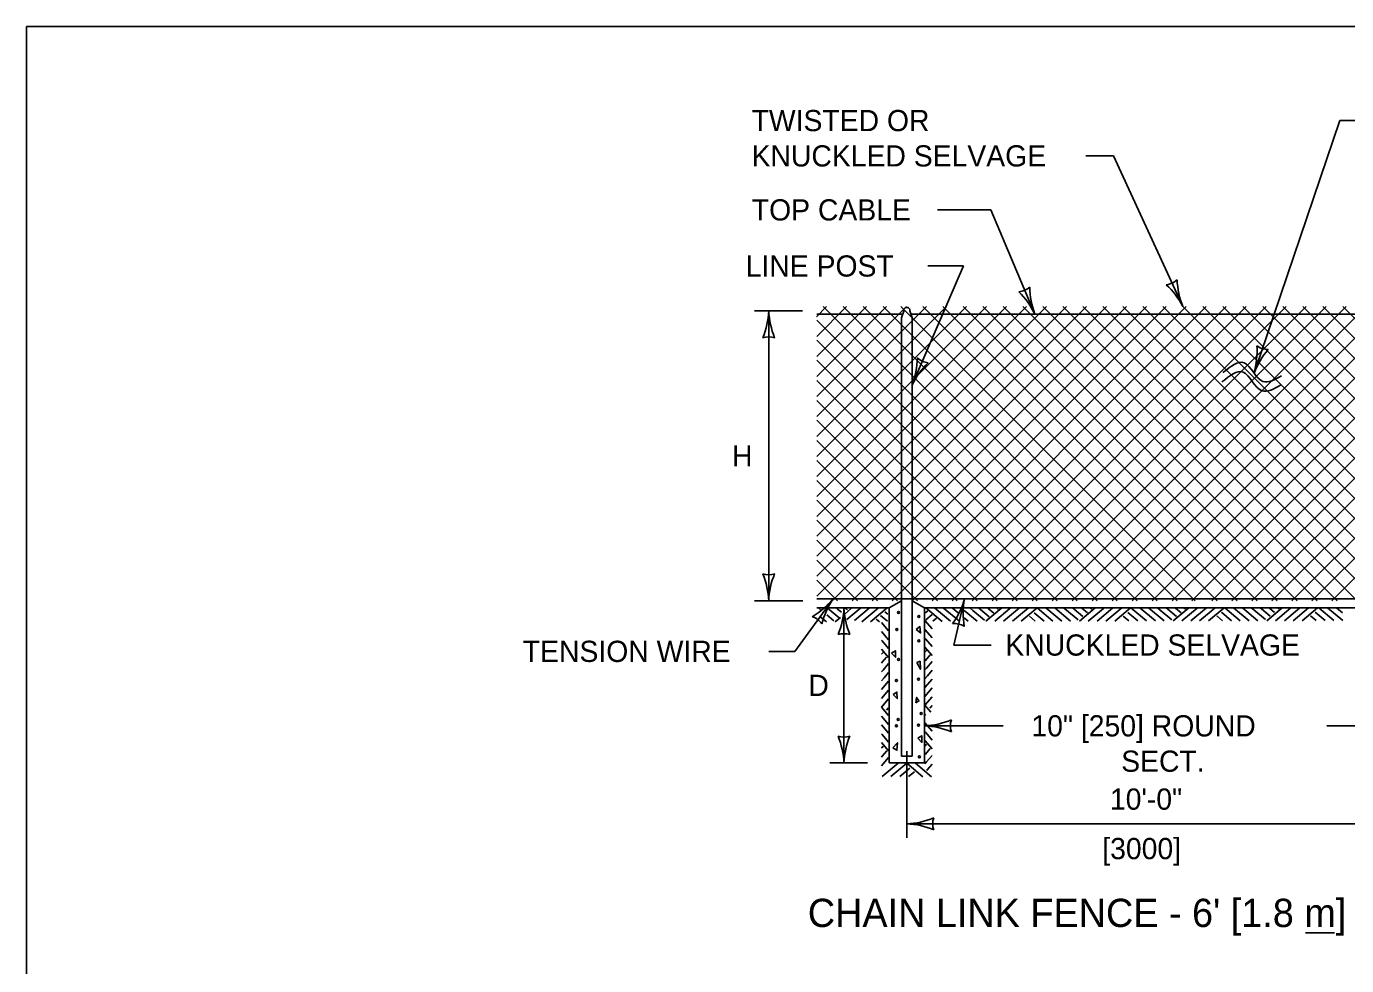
# Model space of a CAD drawing. Extents: x 49973.1 to 50021, y 49987.6 to 50015.4.
# Drawn here: x 49999.384 to 50003.121, y 49996.342 to 49998.999 of the extents above; entities that cross this region are included whole.
import ezdxf

# ---------------------------------------------------------------- set-up
doc = ezdxf.new("R2010")
doc.units = 0
for name, color, linetype in [('Level 1', 7, 'Continuous'), ('Level 2', 7, 'Continuous'), ('Level 3', 7, 'Continuous'), ('Level 6', 7, 'Continuous')]:
    doc.layers.add(name, color=color, linetype=linetype)

msp = doc.modelspace()

# ---------------------------------------------------------------- linework, layer by layer
at = {"layer": 'Level 1'}
for p, q in [((50001.62, 49998.1775), (50001.6487, 49998.2062)), ((50001.6208, 49998.1217), (50001.7053, 49998.2062)), ((50001.6208, 49998.0651), (50001.7619, 49998.2062)), ((50001.6208, 49998.0085), (50001.8185, 49998.2062)), ((50001.6209, 49997.9522), (50001.8749, 49998.2062)), ((50001.6209, 49997.8956), (50001.9315, 49998.2062)), ((50001.6209, 49997.6692), (50002.1579, 49998.2062)), ((50001.6209, 49997.6128), (50002.2143, 49998.2062)), ((50001.6209, 49997.7824), (50002.0447, 49998.2062)), ((50001.6209, 49997.7258), (50002.1013, 49998.2062)), ((50001.6209, 49997.839), (50001.9881, 49998.2062)), ((50001.621, 49997.5563), (50002.2709, 49998.2062)), ((50001.621, 49997.4431), (50002.3841, 49998.2062)), ((50001.621, 49997.4997), (50002.3275, 49998.2062)), ((50001.621, 49997.3865), (50002.4407, 49998.2062)), ((50001.639, 49998.2062), (50002.4716, 49997.3738)), ((50001.6649, 49997.3738), (50002.4973, 49998.2062)), ((50001.6958, 49998.2062), (50002.5282, 49997.3738)), ((50001.7215, 49997.3738), (50002.5539, 49998.2062)), ((50001.7522, 49998.2062), (50002.5848, 49997.3738)), ((50001.7779, 49997.3738), (50002.6103, 49998.2062)), ((50001.8088, 49998.2062), (50002.6414, 49997.3738)), ((50001.8345, 49997.3738), (50002.6669, 49998.2062)), ((50001.8593, 49998.2062), (50002.6922, 49997.3738)), ((50001.8608, 49998.1741), (50001.8671, 49998.1936)), ((50001.8908, 49998.1741), (50001.8848, 49998.1939)), ((50001.8911, 49997.3738), (50002.7235, 49998.2062)), ((50001.9213, 49998.2062), (50002.7544, 49997.3738)), ((50001.9477, 49997.3738), (50002.7801, 49998.2062)), ((50001.9781, 49998.2062), (50002.811, 49997.3738)), ((50002.0043, 49997.3738), (50002.8367, 49998.2062)), ((50002.0349, 49998.2062), (50002.8676, 49997.3738)), ((50002.0609, 49997.3738), (50002.8933, 49998.2062)), ((50002.0913, 49998.2062), (50002.9242, 49997.3738)), ((50002.1173, 49997.3738), (50002.9497, 49998.2062)), ((50002.1482, 49998.2062), (50002.9808, 49997.3738)), ((50002.1739, 49997.3738), (50003.0063, 49998.2062)), ((50002.2043, 49998.2062), (50003.0372, 49997.3738)), ((50002.2305, 49997.3738), (50003.0629, 49998.2062)), ((50002.2607, 49998.2062), (50003.0938, 49997.3738)), ((50002.2871, 49997.3738), (50003.1195, 49998.2062)), ((50002.3178, 49998.2062), (50003.1504, 49997.3738)), ((50002.3437, 49997.3738), (50003.1761, 49998.2062)), ((50002.3741, 49998.2062), (50003.207, 49997.3738)), ((50002.4003, 49997.3738), (50003.2327, 49998.2062)), ((50002.431, 49998.2062), (50003.2636, 49997.3738)), ((50002.4567, 49997.3738), (50003.2891, 49998.2062)), ((50002.4876, 49998.2062), (50003.3202, 49997.3738)), ((50002.5133, 49997.3738), (50003.3457, 49998.2062)), ((50002.5441, 49998.2062), (50003.3768, 49997.3738)), ((50002.5699, 49997.3738), (50003.4023, 49998.2062)), ((50002.6006, 49998.2062), (50003.4332, 49997.3738)), ((50002.6265, 49997.3738), (50003.4589, 49998.2062)), ((50002.6574, 49998.2062), (50003.4898, 49997.3738)), ((50002.6831, 49997.3738), (50003.5155, 49998.2062)), ((50002.7139, 49998.2062), (50003.5464, 49997.3738)), ((50002.7397, 49997.3738), (50003.5721, 49998.2062)), ((50002.7705, 49998.2062), (50003.603, 49997.3738)), ((50002.7963, 49997.3738), (50003.6287, 49998.2062)), ((50002.8271, 49998.2062), (50003.6596, 49997.3738)), ((50002.8527, 49997.3738), (50003.6851, 49998.2062)), ((50002.8837, 49998.2062), (50003.7162, 49997.3738)), ((50002.9093, 49997.3738), (50003.7417, 49998.2062)), ((50002.9401, 49998.2062), (50003.7726, 49997.3738)), ((50002.9659, 49997.3738), (50003.7983, 49998.2062)), ((50002.9967, 49998.2062), (50003.8292, 49997.3738)), ((50003.0225, 49997.3738), (50003.8549, 49998.2062)), ((50003.0533, 49998.2062), (50003.8858, 49997.3738)), ((50003.0791, 49997.3738), (50003.9115, 49998.2062)), ((50003.1099, 49998.2062), (50003.9424, 49997.3738)), ((50001.6208, 49998.1849), (50001.8643, 49998.1849)), ((50001.6208, 49998.1677), (50002.415, 49997.3738)), ((50001.8608, 49998.1741), (50001.8608, 49996.9341)), ((50001.8875, 49998.1849), (50003.2643, 49998.1849)), ((50001.8908, 49998.1741), (50001.8908, 49996.9341)), ((50001.6208, 49998.1111), (50002.3584, 49997.3738)), ((50001.6208, 49998.0543), (50002.3018, 49997.3738)), ((50001.6208, 49997.9975), (50002.2452, 49997.3738)), ((50001.6209, 49997.941), (50002.1886, 49997.3738)), ((50001.6209, 49997.8847), (50002.132, 49997.3738)), ((50001.6209, 49997.8275), (50002.0754, 49997.3738)), ((50001.6209, 49997.7712), (50002.0188, 49997.3738)), ((50001.6209, 49997.7147), (50001.9622, 49997.3738)), ((50001.6209, 49997.6584), (50001.9056, 49997.3738)), ((50001.6209, 49997.6017), (50001.849, 49997.3738)), ((50001.621, 49997.5451), (50001.7924, 49997.3738)), ((50001.621, 49997.4885), (50001.7358, 49997.3738)), ((50001.621, 49997.4319), (50001.6792, 49997.3738)), ((50001.6211, 49997.3795), (50004.6137, 49997.3795)), ((50001.8258, 49997.3541), (50001.8608, 49997.3741)), ((50001.9258, 49997.354), (50001.8908, 49997.3734)), ((50001.621, 49997.3541), (50001.8258, 49997.3541)), ((50001.6316, 49997.3487), (50001.6266, 49997.3529)), ((50001.6481, 49997.314), (50001.6293, 49997.3297)), ((50001.6317, 49997.3487), (50001.6317, 49997.3487)), ((50001.6691, 49997.3175), (50001.6491, 49997.3342)), ((50001.6504, 49997.354), (50001.6503, 49997.3541)), ((50001.684, 49997.3259), (50001.6506, 49997.3541)), ((50001.6797, 49997.3504), (50001.6758, 49997.3537)), ((50001.6907, 49997.3412), (50001.6797, 49997.3504)), ((50001.7009, 49997.3374), (50001.7193, 49997.3528)), ((50001.7031, 49997.3517), (50001.701, 49997.3534)), ((50001.7081, 49997.3475), (50001.7031, 49997.3517)), ((50001.7057, 49997.3205), (50001.7458, 49997.3541)), ((50001.7275, 49997.3179), (50001.7693, 49997.3528)), ((50001.7382, 49997.3477), (50001.7411, 49997.3501)), ((50001.7411, 49997.3501), (50001.7437, 49997.3523)), ((50001.7481, 49997.314), (50001.7959, 49997.3541)), ((50001.7731, 49997.314), (50001.8201, 49997.3535)), ((50001.8208, 49997.3159), (50001.801, 49997.3326)), ((50001.8219, 49997.336), (50001.8139, 49997.3427)), ((50001.8258, 49997.3541), (50001.8258, 49996.915)), ((50001.9258, 49997.3541), (50003.2258, 49997.3541)), ((50001.9258, 49996.915), (50001.9258, 49997.354)), ((50001.9284, 49997.3402), (50001.935, 49997.3457)), ((50001.9296, 49997.3202), (50001.9475, 49997.3352)), ((50001.9757, 49997.3149), (50001.9297, 49997.3535)), ((50001.9995, 49997.3159), (50001.9539, 49997.3541)), ((50002.0245, 49997.3159), (50001.9791, 49997.354)), ((50002.0208, 49997.34), (50002.004, 49997.354)), ((50002.0745, 49997.3159), (50002.038, 49997.3465)), ((50002.0631, 49997.3464), (50002.0539, 49997.354)), ((50002.0954, 49997.3193), (50002.0631, 49997.3464)), ((50002.0847, 49997.3493), (50002.079, 49997.354)), ((50002.1093, 49997.3287), (50002.0847, 49997.3493)), ((50002.0995, 49997.3159), (50002.1448, 49997.354)), ((50002.1061, 49997.3523), (50002.104, 49997.354)), ((50002.1218, 49997.3392), (50002.1061, 49997.3523)), ((50002.1245, 49997.3159), (50002.1675, 49997.352)), ((50002.1295, 49997.3536), (50002.129, 49997.354)), ((50002.1345, 49997.3494), (50002.1295, 49997.3536)), ((50002.1495, 49997.3159), (50002.1948, 49997.354)), ((50002.1675, 49997.352), (50002.1698, 49997.354)), ((50002.1745, 49997.3159), (50002.2198, 49997.354)), ((50002.1995, 49997.3159), (50002.2448, 49997.354)), ((50002.2396, 49997.3164), (50002.2233, 49997.3301)), ((50002.2646, 49997.3164), (50002.2362, 49997.3402)), ((50002.2896, 49997.3164), (50002.2448, 49997.354)), ((50002.3146, 49997.3164), (50002.2696, 49997.354)), ((50002.3396, 49997.3164), (50002.2946, 49997.354)), ((50002.3282, 49997.3469), (50002.3196, 49997.354)), ((50002.3605, 49997.3198), (50002.3282, 49997.3469)), ((50002.3498, 49997.3498), (50002.3447, 49997.354)), ((50002.3744, 49997.3292), (50002.3498, 49997.3498)), ((50002.3646, 49997.3164), (50002.4093, 49997.354)), ((50002.3712, 49997.3528), (50002.3697, 49997.354)), ((50002.3869, 49997.3397), (50002.3712, 49997.3528)), ((50002.3896, 49997.3164), (50002.4326, 49997.3525)), ((50002.3996, 49997.3499), (50002.3946, 49997.3541)), ((50002.4146, 49997.3164), (50002.4593, 49997.354)), ((50002.4326, 49997.3525), (50002.4343, 49997.354)), ((50002.4396, 49997.3164), (50002.4843, 49997.354)), ((50002.4646, 49997.3164), (50002.5093, 49997.354)), ((50002.5047, 49997.3169), (50002.4884, 49997.3306)), ((50002.5297, 49997.3169), (50002.5013, 49997.3407)), ((50002.5547, 49997.3169), (50002.5104, 49997.354)), ((50002.5797, 49997.3169), (50002.5353, 49997.354)), ((50002.6047, 49997.3169), (50002.5603, 49997.354)), ((50002.5933, 49997.3474), (50002.5853, 49997.354)), ((50002.6256, 49997.3203), (50002.5933, 49997.3474)), ((50002.6149, 49997.3503), (50002.6104, 49997.354)), ((50002.6395, 49997.3297), (50002.6149, 49997.3503)), ((50002.6297, 49997.3169), (50002.6738, 49997.354)), ((50002.6363, 49997.3533), (50002.6354, 49997.354)), ((50002.652, 49997.3402), (50002.6363, 49997.3533)), ((50002.6547, 49997.3169), (50002.6977, 49997.353)), ((50002.6647, 49997.3504), (50002.6604, 49997.354)), ((50002.6797, 49997.3169), (50002.7238, 49997.354)), ((50002.6977, 49997.353), (50002.6988, 49997.354)), ((50002.7047, 49997.3169), (50002.7488, 49997.354)), ((50002.7297, 49997.3169), (50002.7738, 49997.354)), ((50002.7698, 49997.3174), (50002.7535, 49997.3311)), ((50002.7948, 49997.3174), (50002.7664, 49997.3412)), ((50002.8198, 49997.3174), (50002.7761, 49997.354)), ((50002.8448, 49997.3174), (50002.801, 49997.354)), ((50002.8698, 49997.3174), (50002.826, 49997.354)), ((50002.8584, 49997.3479), (50002.851, 49997.354)), ((50002.8907, 49997.3208), (50002.8584, 49997.3479)), ((50002.88, 49997.3508), (50002.8761, 49997.354)), ((50002.9046, 49997.3302), (50002.88, 49997.3508)), ((50002.8948, 49997.3174), (50002.9383, 49997.354)), ((50002.9014, 49997.3538), (50002.9011, 49997.354)), ((50002.9171, 49997.3407), (50002.9014, 49997.3538)), ((50002.9198, 49997.3174), (50002.9628, 49997.3535)), ((50002.9298, 49997.3509), (50002.9261, 49997.354)), ((50002.9448, 49997.3174), (50002.9883, 49997.354)), ((50002.9628, 49997.3535), (50002.9633, 49997.354)), ((50002.9698, 49997.3174), (50003.0133, 49997.354)), ((50002.9948, 49997.3174), (50003.0383, 49997.354)), ((50003.0349, 49997.3179), (50003.0186, 49997.3316)), ((50003.0599, 49997.3179), (50003.0315, 49997.3417)), ((50003.0849, 49997.3179), (50003.0418, 49997.354)), ((50003.1099, 49997.3179), (50003.0667, 49997.354)), ((50003.1091, 49997.3395), (50003.0917, 49997.354)), ((50001.6731, 49997.314), (50001.6877, 49997.3263)), ((50001.7981, 49997.314), (50001.7888, 49997.3218)), ((50001.8242, 49997.2884), (50001.8043, 49997.3121)), ((50001.9471, 49997.2943), (50001.9272, 49997.318)), ((50001.9471, 49997.2693), (50001.9272, 49997.293)), ((50001.9495, 49997.3159), (50001.9597, 49997.3244)), ((50002.0495, 49997.3159), (50002.038, 49997.3255)), ((50001.8242, 49997.2634), (50001.8043, 49997.2871)), ((50001.8058, 49997.2604), (50001.8043, 49997.2621)), ((50001.8242, 49997.2384), (50001.8058, 49997.2604)), ((50001.9287, 49997.2663), (50001.9272, 49997.268)), ((50001.9471, 49997.2443), (50001.9287, 49997.2663)), ((50001.8084, 49997.2274), (50001.8042, 49997.2224)), ((50001.8242, 49997.2134), (50001.8043, 49997.2371)), ((50001.9313, 49997.2333), (50001.9271, 49997.2283)), ((50001.9471, 49997.2193), (50001.9272, 49997.243)), ((50001.9415, 49997.2206), (50001.9284, 49997.2049)), ((50001.8055, 49997.199), (50001.8043, 49997.1975)), ((50001.8186, 49997.2147), (50001.8055, 49997.199)), ((50001.8242, 49997.1963), (50001.8085, 49997.1776)), ((50001.9284, 49997.2049), (50001.9272, 49997.2034)), ((50001.9314, 49997.1835), (50001.9272, 49997.1784)), ((50001.9471, 49997.2022), (50001.9314, 49997.1835)), ((50001.8085, 49997.1776), (50001.8043, 49997.1725)), ((50001.8114, 49997.156), (50001.8043, 49997.1474)), ((50001.8242, 49997.1462), (50001.8043, 49997.1224)), ((50001.8242, 49997.1712), (50001.8114, 49997.156)), ((50001.9343, 49997.1619), (50001.9272, 49997.1533)), ((50001.9471, 49997.1521), (50001.9272, 49997.1283)), ((50001.9471, 49997.1771), (50001.9343, 49997.1619)), ((50001.8242, 49997.1212), (50001.8043, 49997.0974)), ((50001.9471, 49997.1271), (50001.9272, 49997.1033)), ((50001.8242, 49997.0963), (50001.8043, 49997.0726)), ((50001.8242, 49997.0489), (50001.8043, 49997.0726)), ((50001.8242, 49997.0712), (50001.8181, 49997.064)), ((50001.9471, 49997.1022), (50001.9272, 49997.0785)), ((50001.944, 49997.0585), (50001.9272, 49997.0785)), ((50001.9471, 49997.0771), (50001.941, 49997.0699)), ((50001.8242, 49997.0239), (50001.8043, 49997.0476)), ((50001.9296, 49997.0506), (50001.9272, 49997.0535)), ((50001.8242, 49996.9989), (50001.8043, 49997.0226)), ((50001.8063, 49996.9953), (50001.8043, 49996.9976)), ((50001.8242, 49996.9739), (50001.8063, 49996.9953)), ((50001.9471, 49997.0048), (50001.9272, 49997.0285)), ((50001.9292, 49997.0012), (50001.9272, 49997.0035)), ((50001.9471, 49996.9798), (50001.9292, 49997.0012)), ((50001.8242, 49996.9489), (50001.8043, 49996.9726)), ((50001.8047, 49996.9573), (50001.8043, 49996.9568)), ((50001.8089, 49996.9623), (50001.8047, 49996.9573)), ((50001.9471, 49996.9548), (50001.9272, 49996.9785)), ((50001.9276, 49996.9632), (50001.9272, 49996.9627)), ((50001.9318, 49996.9682), (50001.9276, 49996.9632)), ((50001.942, 49996.9555), (50001.9289, 49996.9398)), ((50001.806, 49996.9339), (50001.8043, 49996.9318)), ((50001.8191, 49996.9496), (50001.806, 49996.9339)), ((50001.8242, 49996.9306), (50001.809, 49996.9125)), ((50001.8608, 49996.9341), (50001.8908, 49996.9341)), ((50001.9289, 49996.9398), (50001.9272, 49996.9377)), ((50001.9319, 49996.9184), (50001.9272, 49996.9127)), ((50001.9471, 49996.9365), (50001.9319, 49996.9184)), ((50001.809, 49996.9125), (50001.8043, 49996.9068)), ((50001.8059, 49996.8766), (50001.8509, 49996.9142)), ((50001.8258, 49996.915), (50001.9258, 49996.915)), ((50001.8309, 49996.8766), (50001.8757, 49996.9142)), ((50001.8559, 49996.8766), (50001.8843, 49996.9004)), ((50001.921, 49996.8761), (50001.8757, 49996.9142)), ((50001.8809, 49996.8766), (50001.8972, 49996.8903)), ((50001.946, 49996.8761), (50001.9007, 49996.9142)), ((50001.9348, 49996.8968), (50001.9324, 49996.8939)), ((50001.9471, 49996.9114), (50001.9348, 49996.8968))]:
    msp.add_line(p, q, dxfattribs=at)
for points in [[(49999.3835, 49998.9992), (50016.7501, 49998.9992), (50016.7501, 49987.7988), (49999.3835, 49987.7988)], [(50001.9018, 49997.2928), (50001.9128, 49997.301), (50001.9149, 49997.2831)], [(50001.8323, 49997.2258), (50001.8433, 49997.2327), (50001.844, 49997.2142)], [(50001.9039, 49997.1995), (50001.9135, 49997.203), (50001.9142, 49997.1803)], [(50001.8368, 49997.1087), (50001.8478, 49997.1156), (50001.8485, 49997.0971)], [(50001.9013, 49997.0848), (50001.9034, 49997.1005), (50001.9102, 49997.0903)], [(50001.8366, 49996.9577), (50001.849, 49996.9721), (50001.8476, 49996.9509)], [(50001.907, 49996.9849), (50001.918, 49996.9918), (50001.9187, 49996.9733)]]:
    msp.add_lwpolyline(points, close=True, dxfattribs=at)
for centre in [(50001.8526, 49997.3408), (50001.91, 49997.3293), (50001.8475, 49997.2923), (50001.91, 49997.2604), (50001.8526, 49997.208), (50001.8462, 49997.148), (50001.9088, 49997.1519), (50001.8513, 49997.0382), (50001.9164, 49997.0548), (50001.8462, 49997.0204), (50001.9088, 49997.0217), (50001.9113, 49996.9323)]:
    msp.add_circle(centre, 0.00279, dxfattribs=at)
msp.add_arc((50001.8759, 49998.1951), 0.00895, 352.3754, 189.572, dxfattribs=at)
at = {"layer": 'Level 2'}
msp.add_line((50003.0863, 49996.4347), (50003.0044, 49996.4347), dxfattribs=at)
at = {"layer": 'Level 3'}
for p, q in [((50002.8588, 49998.018), (50003.1019, 49998.7328)), ((50003.1019, 49998.7328), (50003.2208, 49998.7328)), ((50002.4613, 49998.6328), (50002.3825, 49998.6328)), ((50002.6574, 49998.2062), (50002.4613, 49998.6328)), ((50002.1132, 49998.48), (50001.9625, 49998.48)), ((50002.2382, 49998.1849), (50002.1132, 49998.48)), ((50001.8908, 49997.9845), (50002.0365, 49998.3213)), ((50002.0365, 49998.3213), (50001.9349, 49998.3213)), ((50001.5808, 49998.1941), (50001.4449, 49998.1941)), ((50001.4849, 49997.3741), (50001.4849, 49998.1941)), ((50001.5811, 49997.3741), (50001.4449, 49997.3741)), ((50001.6674, 49997.3795), (50001.5585, 49997.2308)), ((50002.0391, 49997.3795), (50002.0085, 49997.2481)), ((50001.6979, 49996.915), (50001.6979, 49997.3541)), ((50001.5585, 49997.2308), (50001.4849, 49997.2308)), ((50002.0085, 49997.2481), (50002.1146, 49997.2481)), ((50002.1483, 49997.02), (50001.9258, 49997.02)), ((50003.065, 49997.02), (50003.2258, 49997.02)), ((50001.8758, 49996.948), (50001.8758, 49996.7027)), ((50001.7643, 49996.915), (50001.6579, 49996.915)), ((50001.8758, 49996.7427), (50003.2767, 49996.7427))]:
    msp.add_line(p, q, dxfattribs=at)
for centre, radius, start, end in [((50002.6039, 49998.3227), 0.0548, 276.8211, 312.5434), ((50002.4507, 49998.0986), 0.233, 27.5096, 46.7594), ((50002.8631, 49998.2907), 0.2223, 182.1383, 202.3218), ((50002.1882, 49998.303), 0.0548, 275.0872, 310.8096), ((50002.0284, 49998.0836), 0.233, 25.7757, 45.0255), ((50002.4463, 49998.2631), 0.2223, 180.4044, 200.5879), ((50001.2628, 49998.2033), 0.2223, 337.456, 357.6395), ((50001.7176, 49998.2056), 0.233, 182.8273, 202.0772), ((50001.4849, 49998.0659), 0.0548, 72.1388, 107.8612), ((50002.6345, 49998.0814), 0.233, 344.2336, 3.4835), ((50003.0664, 49997.9385), 0.2223, 138.8623, 159.0459), ((50002.8997, 49998.1396), 0.0548, 233.5452, 269.2675), ((50001.6727, 49998.0664), 0.233, 339.4345, 358.6844), ((50002.091, 49997.8879), 0.2223, 134.0632, 154.2467), ((50001.9417, 49998.1022), 0.0548, 228.746, 264.4684), ((50001.4849, 49997.5023), 0.0548, 252.1388, 287.8612), ((50001.2522, 49997.3626), 0.233, 2.8273, 22.0772), ((50001.707, 49997.365), 0.2223, 157.456, 177.6395), ((50001.4954, 49997.5204), 0.2223, 300.5072, 320.6907), ((50001.8603, 49997.2488), 0.233, 145.8785, 165.1283), ((50001.8248, 49997.4388), 0.2223, 324.3468, 344.5303), ((50002.2683, 49997.3379), 0.233, 169.7181, 188.968), ((50001.4758, 49997.3633), 0.2223, 337.456, 357.6395), ((50001.9306, 49997.3656), 0.233, 182.8273, 202.0772), ((50001.5903, 49997.2771), 0.0548, 35.19, 70.9123), ((50002.01, 49997.2547), 0.0548, 59.0296, 94.752), ((50001.6979, 49997.2259), 0.0548, 72.1388, 107.8612), ((50001.9143, 49997.2527), 0.233, 272.8273, 292.0772), ((50002.054, 49997.02), 0.0548, 162.1388, 197.8612), ((50001.9166, 49996.7979), 0.2223, 67.456, 87.6395), ((50001.6979, 49997.0432), 0.0548, 252.1388, 287.8612), ((50001.4652, 49996.9035), 0.233, 2.8273, 22.0772), ((50001.92, 49996.9059), 0.2223, 157.456, 177.6395), ((50001.8643, 49996.9754), 0.233, 272.8273, 292.0772), ((50001.8666, 49996.5206), 0.2223, 67.456, 87.6395), ((50002.004, 49996.7427), 0.0548, 162.1388, 197.8612)]:
    msp.add_arc(centre, radius, start, end, dxfattribs=at)
at = {"layer": 'Level 6'}
for points in [[(50002.7705, 49998.0195), (50002.8307, 49998.0474), (50002.8837, 49997.9946), (50002.9366, 49998.0107)], [(50002.7676, 49997.9931), (50002.8278, 49998.021), (50002.8808, 49997.9682), (50002.9337, 49997.9843)]]:
    msp.add_spline(points, degree=3, dxfattribs=at)

# ---------------------------------------------------------------- texts
at = {"layer": 'Level 2'}
for s, height, p in [('TWISTED OR ', 0.06, (50001.4363, 49998.7028)), ('KNUCKLED SELVAGE', 0.06, (50001.4363, 49998.6028)), ('TOP CABLE', 0.06, (50001.437, 49998.45)), ('LINE POST', 0.06, (50001.4197, 49998.2913)), ('H', 0.06, (50001.3809, 49997.7541)), ('TENSION WIRE', 0.06, (50000.7887, 49997.2008)), ('KNUCKLED SELVAGE', 0.06, (50002.1546, 49997.2187)), ('D', 0.06, (50001.5972, 49997.1046)), ('10" [250] ROUND', 0.06, (50002.2285, 49996.99)), ('SECT.', 0.06, (50002.4827, 49996.89)), ('10\'-0"', 0.06, (50002.4508, 49996.7827)), ('[3000]', 0.06, (50002.4291, 49996.6427)), ("CHAIN LINK FENCE - 6' [1.8 m] AND 8' [2.4 m]", 0.08, (50001.5955, 49996.4507))]:
    msp.add_text(s, height=height, dxfattribs=at).set_placement(p)

doc.saveas('drawing.dxf')
